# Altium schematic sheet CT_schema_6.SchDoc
size 278 x 236 mm
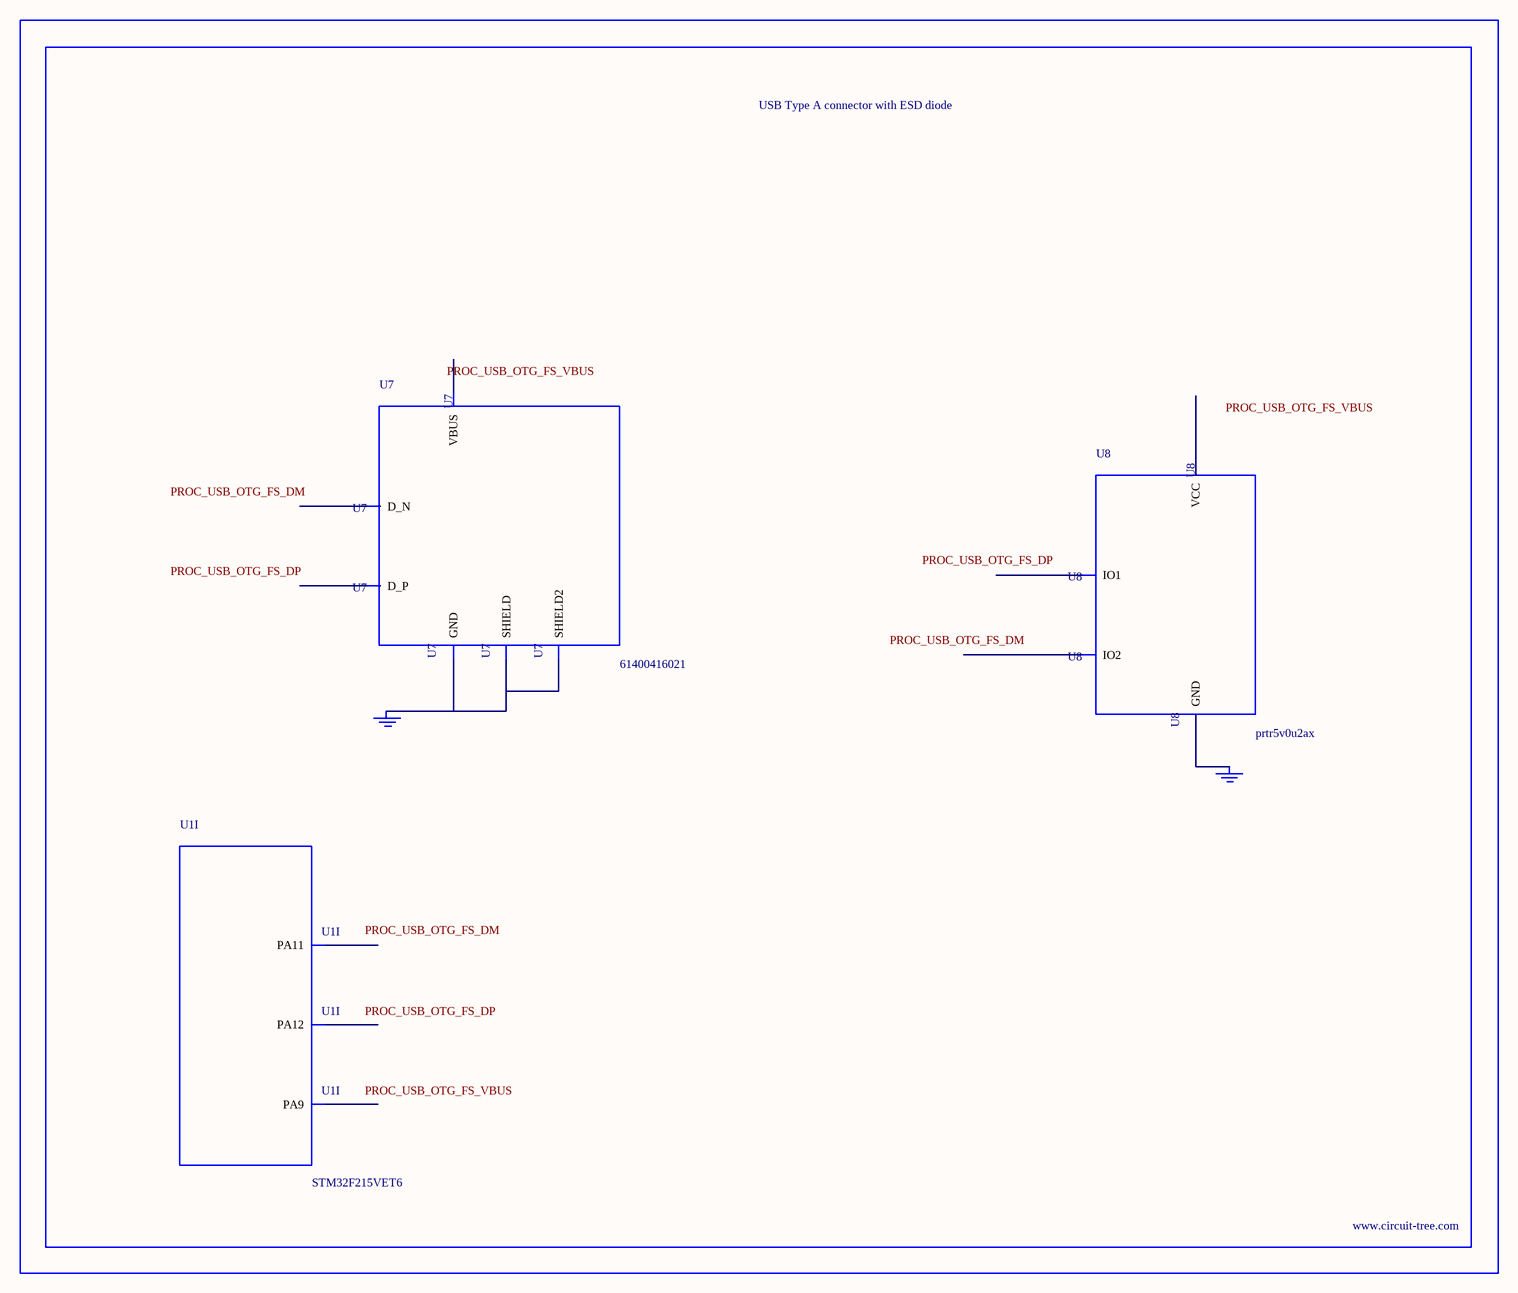
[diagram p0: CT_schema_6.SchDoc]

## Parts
BORDER5  (no value)
GND_INSTANCE_5_0  (no value)
GND_INSTANCE_5_1  (no value)
U1  STM32F215VET6  [LQFP100]  (part I of 9)
U7  61400416021  [USB-A-H]
U8  prtr5v0u2ax  [SOT143B]

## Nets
NetGND_INSTANCE_5_0_0: GND_INSTANCE_5_0.0(GND) U7.4(GND) U7.5(SHIELD) U7.6(SHIELD2)
NetGND_INSTANCE_5_1_0: GND_INSTANCE_5_1.0(GND) U8.1(GND)

Not connected (* = marked no-connect by the designer): U1 68(PA9) 70(PA11) 71(PA12); U7 1(VBUS) 2(D_N) 3(D_P); U8 2(IO1) 3(IO2) 4(VCC)

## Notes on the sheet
- Labels drawn without touching a wire or pin: PROC_USB_OTG_FS_DM, PROC_USB_OTG_FS_DP, PROC_USB_OTG_FS_VBUS

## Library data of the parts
BORDER5 = BORDER_PAGE5
GND_INSTANCE_5_0 GND_INSTANCE_5_1 = GND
